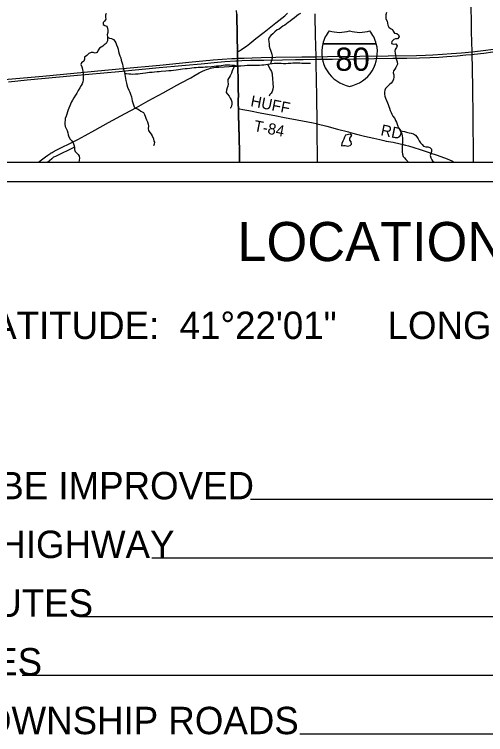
# Model space of a CAD drawing. Extents: x 0 to 34, y 0 to 22.
# Drawn here: x 3.288 to 5.694, y 11.175 to 14.854 of the extents above; entities that cross this region are included whole.
import ezdxf

# ---------------------------------------------------------------- set-up
doc = ezdxf.new("R2010")
doc.units = 0
for name, color, linetype in [('GM_X_Corporation', 7, 'Continuous'), ('GM_X_County_Road', 7, 'Continuous'), ('GM_X_Interstate_Location', 7, 'Continuous'), ('GM_X_Interstate_Route', 7, 'Continuous'), ('GM_X_Interstate_Shield', 7, 'Continuous'), ('GM_X_Minor_Lake', 7, 'Continuous'), ('GM_X_Minor_River', 7, 'Continuous'), ('GM_X_Township_Road', 7, 'Continuous'), ('GM_X_Township_Road_Text', 7, 'Continuous'), ('SH_Data', 7, 'Continuous'), ('SH_Text', 7, 'Continuous')]:
    doc.layers.add(name, color=color, linetype=linetype)

msp = doc.modelspace()

# ---------------------------------------------------------------- linework, layer by layer
at = {"layer": 'GM_X_Corporation'}
for points in [[(2.1, 20.7089), (2.1, 14.1), (8.9, 14.1), (8.9, 18.9067)], [(2.1, 16.8894), (2.1, 14.1), (4.4374, 14.1), (4.437, 14.154), (4.4348, 14.2876), (4.4332, 14.3373), (4.4327, 14.3684), (4.4325, 14.3733), (4.4317, 14.396), (4.4315, 14.4227), (4.4318, 14.4347), (4.431, 14.4741), (4.4301, 14.5114), (4.4285, 14.5905), (4.4282, 14.5944), (4.4282, 14.6082), (4.4279, 14.6184), (4.4276, 14.6307), (4.4274, 14.64), (4.4269, 14.6591), (4.427, 14.6635), (4.4253, 14.7443), (4.4234, 14.8562)], [(4.4234, 14.8562), (4.4253, 14.7443), (4.427, 14.6635), (4.4269, 14.6591), (4.4274, 14.64), (4.4276, 14.6307), (4.4279, 14.6184), (4.4282, 14.6082), (4.4282, 14.5944), (4.4285, 14.5905), (4.4301, 14.5114), (4.431, 14.4741), (4.4318, 14.4347), (4.4315, 14.4227), (4.4317, 14.396), (4.4325, 14.3733), (4.4327, 14.3684), (4.4332, 14.3373), (4.4348, 14.2876), (4.437, 14.154), (4.4374, 14.1), (8.9, 14.1), (8.9, 16.8293)]]:
    msp.add_lwpolyline(points, dxfattribs=at)
at = {"layer": 'GM_X_County_Road'}
for points in [[(4.4272, 14.6629), (4.4314, 14.6655), (4.437, 14.6682), (4.4477, 14.6746), (4.4606, 14.6831), (4.4732, 14.6921), (4.4904, 14.7053), (4.5217, 14.7306), (4.5629, 14.7632), (4.6233, 14.8111), (4.6689, 14.8478), (4.6835, 14.8602)], [(4.4287, 14.5899), (4.4285, 14.5939), (4.4284, 14.6077), (4.4281, 14.6178), (4.4278, 14.6302), (4.4276, 14.6394), (4.4271, 14.6586), (4.4272, 14.6629)], [(3.4111, 14.1), (3.4199, 14.1063), (3.4471, 14.1269), (3.4598, 14.1358), (3.4744, 14.1451), (3.4761, 14.1465), (3.4806, 14.1494), (3.4859, 14.1523), (3.5022, 14.1607), (3.5985, 14.2083), (3.6116, 14.2154), (3.6495, 14.2364), (3.6987, 14.2629), (3.7696, 14.3016), (3.8542, 14.3476), (3.9114, 14.3789), (3.971, 14.4121), (4.0474, 14.4537), (4.1181, 14.4924), (4.1399, 14.5041), (4.189, 14.531), (4.2106, 14.5432), (4.2324, 14.5551), (4.2489, 14.5637), (4.2601, 14.5689), (4.2687, 14.5725), (4.2804, 14.5766), (4.2893, 14.5792), (4.2983, 14.5814), (4.3074, 14.5831), (4.3166, 14.5843), (4.332, 14.5856), (4.4127, 14.5895), (4.4235, 14.5898), (4.4287, 14.5899)]]:
    msp.add_lwpolyline(points, dxfattribs=at)
at = {"layer": 'GM_X_Interstate_Route'}
for points in [[(3.217, 14.5193), (3.4336, 14.5396), (3.7493, 14.5694), (3.8421, 14.5779), (4.0309, 14.5957), (4.1794, 14.6098), (4.3032, 14.6215), (4.3497, 14.6253), (4.3993, 14.6286), (4.4179, 14.6295), (4.4278, 14.6302), (4.4614, 14.6315), (4.5018, 14.6332), (4.5484, 14.6343), (4.623, 14.6351), (4.7566, 14.6371), (4.8286, 14.6382), (4.8871, 14.6391), (5.0519, 14.6411), (5.3409, 14.6451), (5.3875, 14.6462), (5.4248, 14.6477), (5.4744, 14.6506), (5.5209, 14.654), (5.5705, 14.6584), (5.6253, 14.6639), (5.6385, 14.6653), (5.6817, 14.6703), (5.7341, 14.6774)], [(3.2576, 14.5102), (3.3535, 14.5193), (3.5917, 14.5419), (3.6691, 14.5494), (3.8208, 14.5633), (3.9043, 14.571), (3.9601, 14.576), (4.0281, 14.5825), (4.1055, 14.5899), (4.1612, 14.5953), (4.2417, 14.6026), (4.3252, 14.6106), (4.3624, 14.6135), (4.4183, 14.6171), (4.4281, 14.6178), (4.4494, 14.6188), (4.496, 14.6202), (4.5613, 14.6213), (4.6576, 14.6226), (4.7229, 14.6235), (4.7633, 14.6241), (4.8254, 14.6249), (4.8288, 14.6249), (4.869, 14.6256), (4.9124, 14.6262), (5.0336, 14.6281), (5.1268, 14.629), (5.2201, 14.6303), (5.2916, 14.6311), (5.3568, 14.6326), (5.4096, 14.6343), (5.4561, 14.6364), (5.4964, 14.6389), (5.5491, 14.643), (5.5924, 14.647), (5.6256, 14.6502), (5.6357, 14.6511), (5.6851, 14.657), (5.7312, 14.6632)]]:
    msp.add_lwpolyline(points, dxfattribs=at)
at = {"layer": 'GM_X_Interstate_Shield'}
for p, q in [((4.8629, 14.7039), (5.1362, 14.7039)), ((5.1362, 14.7039), (4.8629, 14.7039)), ((5.1362, 14.7039), (4.8629, 14.7039))]:
    msp.add_line(p, q, dxfattribs=at)
for centre, start, end in [((5.0351, 14.6604), 141.669, 165.8066), ((4.9477, 14.9403), 253.0091, 286.9909), ((5.0514, 14.9403), 253.0091, 286.9909), ((4.964, 14.6604), 14.1934, 38.331), ((5.0351, 14.6604), 165.8066, 258.463), ((4.964, 14.6604), 281.537, 14.1934)]:
    msp.add_arc(centre, 0.1776, start, end, dxfattribs=at)
at = {"layer": 'GM_X_Minor_Lake'}
for points in [[(4.967, 14.2108), (4.9653, 14.2066), (4.9597, 14.194), (4.9579, 14.1826), (4.9685, 14.1838), (4.978, 14.1842), (4.9913, 14.1809), (5.0023, 14.1851), (5.0099, 14.1913), (5.0071, 14.203), (5.0002, 14.211), (5.0002, 14.222), (5.0069, 14.2293), (5.0118, 14.2377), (5.0023, 14.2426), (4.9784, 14.2371)], [(4.9784, 14.2371), (4.9735, 14.2268), (4.9698, 14.2176), (4.967, 14.2108)]]:
    msp.add_lwpolyline(points, dxfattribs=at)
at = {"layer": 'GM_X_Minor_River'}
for points in [[(3.7569, 14.8597), (3.754, 14.8505), (3.7536, 14.8399), (3.756, 14.8304), (3.7477, 14.8205), (3.7409, 14.8124), (3.7421, 14.8026), (3.7509, 14.7984), (3.76, 14.7939), (3.7639, 14.7848), (3.7655, 14.7723), (3.7648, 14.7613), (3.7622, 14.7498), (3.7631, 14.7396), (3.7639, 14.7293), (3.7636, 14.7187), (3.7561, 14.7061), (3.7474, 14.6988), (3.7395, 14.6923), (3.7312, 14.6869), (3.7221, 14.6819), (3.7168, 14.6709), (3.7104, 14.6598), (3.7002, 14.6559), (3.6907, 14.66)], [(4.7484, 14.8598), (4.7394, 14.8537), (4.728, 14.8453), (4.7182, 14.8361), (4.7073, 14.8276), (4.6967, 14.8204), (4.6857, 14.8134), (4.677, 14.8058), (4.6683, 14.8), (4.6592, 14.7939), (4.6498, 14.7881), (4.6396, 14.7793), (4.6301, 14.7747), (4.6177, 14.7647), (4.6071, 14.7559), (4.598, 14.7471), (4.5897, 14.7372), (4.586, 14.7269), (4.5872, 14.7159), (4.5884, 14.703), (4.5897, 14.6916), (4.592, 14.6806), (4.5955, 14.6711), (4.5998, 14.6608), (4.6036, 14.6514), (4.6052, 14.6415), (4.6038, 14.6308), (4.6008, 14.6183), (4.5958, 14.6017)], [(5.1887, 14.8641), (5.185, 14.8523), (5.1843, 14.8405), (5.1855, 14.831), (5.1909, 14.8204), (5.1933, 14.809), (5.1956, 14.7988), (5.2002, 14.7893), (5.2083, 14.7821), (5.2186, 14.778), (5.2224, 14.7685), (5.2297, 14.7591), (5.2415, 14.7561), (5.2503, 14.7505), (5.2523, 14.7391), (5.2443, 14.7299), (5.2349, 14.7291), (5.225, 14.7264), (5.2152, 14.7164), (5.2137, 14.7065), (5.2244, 14.702), (5.2366, 14.7033), (5.2427, 14.6945), (5.239, 14.685), (5.2326, 14.6759), (5.2311, 14.666), (5.2327, 14.6557), (5.2335, 14.6439), (5.2363, 14.6344), (5.2401, 14.6227), (5.2433, 14.6113), (5.2441, 14.5999), (5.2355, 14.5839), (5.2306, 14.5747), (5.2246, 14.5659), (5.222, 14.5553), (5.2251, 14.5454), (5.2263, 14.5344), (5.2237, 14.5234), (5.2189, 14.5123), (5.2121, 14.5035), (5.2034, 14.497), (5.194, 14.4867), (5.1838, 14.4763), (5.1789, 14.4672), (5.1775, 14.4569), (5.1783, 14.4474), (5.1803, 14.4364), (5.1834, 14.4269), (5.1884, 14.4144), (5.1938, 14.4027), (5.1969, 14.3936), (5.2004, 14.3837), (5.2035, 14.3746), (5.2077, 14.3636), (5.212, 14.3537), (5.2162, 14.345), (5.2212, 14.3348), (5.2308, 14.3219), (5.2347, 14.3124), (5.2386, 14.3033), (5.2424, 14.2935), (5.2467, 14.2836), (5.2513, 14.2738), (5.2563, 14.2643), (5.2621, 14.2533), (5.2663, 14.2438), (5.2687, 14.234)], [(3.7632, 14.7376), (3.7741, 14.7328), (3.7844, 14.7306), (3.7936, 14.7257), (3.8008, 14.7181), (3.8062, 14.7091), (3.8093, 14.6988), (3.8143, 14.6871), (3.8178, 14.6768), (3.8206, 14.6654), (3.8241, 14.6529), (3.8272, 14.6423), (3.8311, 14.632), (3.8342, 14.6214), (3.8373, 14.61), (3.84, 14.5994), (3.842, 14.5899), (3.8443, 14.5789), (3.8475, 14.569), (3.8498, 14.5584), (3.8518, 14.5478), (3.8537, 14.5375), (3.8553, 14.5269), (3.8581, 14.5163), (3.8608, 14.5037), (3.862, 14.4939), (3.8659, 14.4832), (3.8732, 14.4677), (3.8775, 14.4571), (3.8817, 14.4461), (3.8856, 14.4332), (3.888, 14.4229), (3.8899, 14.4134), (3.8938, 14.4021), (3.8973, 14.3922), (3.9004, 14.3827), (3.9069, 14.3748), (3.9164, 14.3714), (3.926, 14.3661), (3.9347, 14.3601), (3.947, 14.353), (3.952, 14.3424), (3.9558, 14.3336), (3.9593, 14.3245), (3.9628, 14.3151), (3.9674, 14.3052), (3.9713, 14.2938), (3.9729, 14.2828), (3.9718, 14.2718), (3.973, 14.2615), (3.9799, 14.2517), (3.9872, 14.2426), (3.9926, 14.2347), (3.9992, 14.2191), (4.0011, 14.207), (4.0031, 14.2013), (4.0028, 14.1906), (3.9983, 14.1822)], [(3.6907, 14.66), (3.6804, 14.6592), (3.6691, 14.6554), (3.6581, 14.6443), (3.6464, 14.6362), (3.6469, 14.6256), (3.6435, 14.6153), (3.6314, 14.6072), (3.6281, 14.5981), (3.6323, 14.5871), (3.6358, 14.5738), (3.6382, 14.5624), (3.6398, 14.5502), (3.6399, 14.5407), (3.6392, 14.5297), (3.6389, 14.5202), (3.6378, 14.5095), (3.6348, 14.5004), (3.6299, 14.4913), (3.6224, 14.4798), (3.6142, 14.4653), (3.607, 14.4523), (3.6003, 14.4409), (3.5924, 14.4287), (3.5852, 14.4168), (3.5796, 14.4077), (3.5751, 14.3959), (3.5718, 14.3867), (3.5669, 14.3757), (3.5628, 14.3669), (3.5594, 14.3566), (3.5557, 14.3452), (3.552, 14.3338), (3.5479, 14.3231), (3.5468, 14.3132), (3.5461, 14.3037), (3.5454, 14.2938), (3.5482, 14.2816), (3.5524, 14.2718), (3.5571, 14.2612), (3.5606, 14.2498), (3.5637, 14.2388), (3.5668, 14.2293), (3.5733, 14.2176), (3.5821, 14.2089), (3.5883, 14.1979), (3.5918, 14.1876), (3.5945, 14.1763), (3.595, 14.1641), (3.5992, 14.1542), (3.6061, 14.1474), (3.6145, 14.1391), (3.6195, 14.1297), (3.6207, 14.1198), (3.6193, 14.1095), (3.6167, 14.1)], [(3.851, 14.5518), (3.8609, 14.552), (3.8723, 14.5506), (3.8825, 14.5503), (3.8932, 14.5496), (3.9068, 14.55), (3.9198, 14.5512), (3.9304, 14.5521), (3.9448, 14.5544), (3.9585, 14.5564), (3.968, 14.5576), (3.9786, 14.5585), (3.9911, 14.5597), (4.0036, 14.5609), (4.0177, 14.5621), (4.0279, 14.563), (4.0374, 14.5638), (4.061, 14.5654), (4.0773, 14.5674), (4.0891, 14.5683), (4.1008, 14.5695), (4.1141, 14.5715), (4.1259, 14.5727), (4.1358, 14.5739), (4.146, 14.5755), (4.1604, 14.5779), (4.171, 14.5783), (4.184, 14.5803), (4.1946, 14.5819), (4.206, 14.5831), (4.2158, 14.5835), (4.2269, 14.5844), (4.2386, 14.5848), (4.2515, 14.5853), (4.2629, 14.5857), (4.2739, 14.5866), (4.2948, 14.5886), (4.3077, 14.5902), (4.321, 14.5914), (4.3313, 14.5922), (4.3438, 14.5935), (4.3548, 14.5947), (4.365, 14.5963), (4.3764, 14.5959), (4.3882, 14.596), (4.3992, 14.5957), (4.4099, 14.5943), (4.4221, 14.5921), (4.4323, 14.5914), (4.4437, 14.5914), (4.4627, 14.5938), (4.476, 14.5947), (4.4878, 14.5947), (4.4988, 14.5948), (4.5094, 14.5953), (4.5193, 14.5953), (4.5292, 14.5954), (4.5402, 14.5955), (4.5512, 14.5959), (4.5626, 14.5971), (4.5728, 14.5983), (4.5823, 14.5999), (4.5926, 14.6011), (4.6043, 14.6031), (4.615, 14.6047), (4.626, 14.6051), (4.6404, 14.6052), (4.6499, 14.6045), (4.6621, 14.6042), (4.6742, 14.6043), (4.6868, 14.6047), (4.7, 14.606), (4.7107, 14.6064), (4.7236, 14.6065), (4.735, 14.6066), (4.7449, 14.6063), (4.7563, 14.6056), (4.7692, 14.6053), (4.7817, 14.605), (4.792, 14.6054), (4.8003, 14.6058)], [(4.4104, 14.5942), (4.4081, 14.5847), (4.401, 14.5657), (4.3961, 14.5535), (4.3901, 14.5409), (4.3841, 14.5317), (4.3789, 14.5222), (4.3786, 14.5104), (4.3798, 14.4998), (4.3787, 14.488), (4.375, 14.4785), (4.372, 14.4667), (4.3698, 14.4556), (4.3771, 14.4465), (4.3855, 14.4363), (4.3902, 14.4265), (4.3948, 14.4178), (4.3979, 14.4083), (4.3987, 14.398), (4.3961, 14.3862), (4.3913, 14.3752), (4.3905, 14.3748)], [(4.5799, 14.5995), (4.5954, 14.5711), (4.6016, 14.5628), (4.6039, 14.5514), (4.6044, 14.5411), (4.6056, 14.5316), (4.606, 14.5202), (4.6073, 14.5092), (4.6085, 14.4993), (4.609, 14.4841), (4.6087, 14.4723), (4.6053, 14.4613), (4.5997, 14.4525), (4.5929, 14.4449), (4.5892, 14.4361)], [(5.259, 14.2591), (5.2696, 14.2583), (5.2799, 14.2553), (5.291, 14.252), (5.3039, 14.2486), (5.3142, 14.2472), (5.3256, 14.2442), (5.3363, 14.2378), (5.3432, 14.2284), (5.3493, 14.2185), (5.3547, 14.2083), (5.3616, 14.1984), (5.3696, 14.1897), (5.3777, 14.1818), (5.3891, 14.1785), (5.3986, 14.1774), (5.4089, 14.174), (5.4173, 14.1661), (5.4174, 14.1547), (5.4137, 14.1437), (5.4118, 14.133), (5.4138, 14.1216), (5.4192, 14.111), (5.4253, 14.1023), (5.4396, 14.1)], [(5.2687, 14.234), (5.2703, 14.223), (5.2707, 14.2127), (5.2704, 14.1998), (5.2682, 14.1868), (5.2683, 14.1739), (5.2684, 14.1621), (5.2689, 14.1519), (5.2697, 14.1401), (5.2736, 14.1283), (5.2793, 14.1208), (5.2874, 14.1124), (5.2946, 14.1053), (5.2956, 14.1)], [(3.5945, 14.176), (3.498, 14.1285), (3.4885, 14.1243), (3.4794, 14.117), (3.4673, 14.1059), (3.4597, 14.1)]]:
    msp.add_lwpolyline(points, dxfattribs=at)
at = {"layer": 'GM_X_Township_Road'}
for points in [[(5.623, 14.7648), (5.6223, 14.7968), (5.6202, 14.9118), (5.6194, 14.9584), (5.6189, 14.9816)], [(4.4272, 14.6629), (4.4255, 14.7437), (4.4236, 14.8556), (4.4231, 14.875)], [(4.8339, 14.2956), (4.8334, 14.3442), (4.8329, 14.3908), (4.8324, 14.4592), (4.8316, 14.4965), (4.8288, 14.6249), (4.8286, 14.6382), (4.8273, 14.6954), (4.825, 14.7469), (4.8238, 14.8477), (4.8233, 14.857)], [(5.6274, 14.5685), (5.6272, 14.5794), (5.6256, 14.6502), (5.6253, 14.6639), (5.623, 14.7648)], [(4.4287, 14.5899), (4.4285, 14.5939), (4.4284, 14.6077), (4.4281, 14.6178), (4.4278, 14.6302), (4.4276, 14.6394), (4.4271, 14.6586), (4.4272, 14.6629)], [(4.4327, 14.3728), (4.4319, 14.3955), (4.4317, 14.4222), (4.432, 14.4341), (4.4312, 14.4736), (4.4303, 14.5108), (4.4287, 14.5899)], [(5.6318, 14.1), (5.6316, 14.204), (5.6313, 14.2506), (5.6309, 14.2941), (5.6304, 14.3377), (5.6302, 14.381), (5.6293, 14.4284), (5.6292, 14.4878), (5.6274, 14.5685)], [(4.4327, 14.3728), (4.4399, 14.3715), (4.4551, 14.3689), (4.4849, 14.3628), (4.5516, 14.3501), (4.6188, 14.3375), (4.6675, 14.3278), (4.7316, 14.3156), (4.814, 14.3001), (4.8292, 14.2968), (4.8339, 14.2956)], [(4.4377, 14.1), (4.4372, 14.1535), (4.435, 14.2871), (4.4334, 14.3368), (4.4329, 14.3679), (4.4327, 14.3728)], [(4.8339, 14.2956), (4.8833, 14.2828), (4.9373, 14.2685), (4.9943, 14.2536), (5.0027, 14.2512), (5.0489, 14.2387), (5.0758, 14.2328), (5.1236, 14.2226), (5.1534, 14.2148), (5.1747, 14.2098), (5.1868, 14.2075), (5.199, 14.2051), (5.2221, 14.2011), (5.2581, 14.1936), (5.2672, 14.1918), (5.2852, 14.187), (5.2999, 14.183), (5.3286, 14.1745), (5.3598, 14.1644), (5.4003, 14.1505), (5.4147, 14.1455), (5.441, 14.1362), (5.4843, 14.1213), (5.4985, 14.1156), (5.5213, 14.1058), (5.5342, 14.1)], [(4.8357, 14.1), (4.8352, 14.1514), (4.8346, 14.2198), (4.8341, 14.2789), (4.8339, 14.2956)]]:
    msp.add_lwpolyline(points, dxfattribs=at)
at = {"layer": 'SH_Data'}
for p, q in [((2.1, 14.1), (8.9, 14.1)), ((2, 14), (9, 14)), ((7.7, 12.3767), (4.4937, 12.3767)), ((7.7, 12.0767), (3.9895, 12.0767)), ((7.7, 11.7767), (3.6192, 11.7767)), ((7.7, 11.4767), (3.3288, 11.4767)), ((7.7, 11.1767), (4.7452, 11.1767))]:
    msp.add_line(p, q, dxfattribs=at)

# ---------------------------------------------------------------- texts
at = {"layer": 'GM_X_Interstate_Location'}
for s in ['-', '.', ',']:
    msp.add_text(s, height=0.000189, dxfattribs=at).set_placement((4.9995, 14.6284))
msp.add_text('80', height=0.000189, rotation=0, dxfattribs=at).set_placement((4.9608, 14.5892))
at = {"layer": 'GM_X_Interstate_Shield'}
msp.add_text('80', height=0.11837, dxfattribs=at).set_placement((4.9268, 14.5663))
at = {"layer": 'GM_X_Township_Road_Text'}
for s, rotation, p in [('HUFF', 348.901, (4.491, 14.3858)), ('T-84', 349.0345, (4.5074, 14.2588)), ('RD', 348.5969, (5.1554, 14.2374))]:
    msp.add_text(s, height=0.05682, rotation=rotation, dxfattribs=at).set_placement(p)
at = {"layer": 'SH_Text'}
for s, height, p in [('LOCATION MAP', 0.2, (4.4269, 13.5938)), ('LATITUDE:  41°22\'01"     LONGITUDE:  82°30\'43"', 0.14, (3.071, 13.1959)), ('PORTION TO BE IMPROVED', 0.14, (1.9944, 12.3767)), ('INTERSTATE HIGHWAY', 0.14, (1.9944, 12.0767)), ('FEDERAL ROUTES', 0.14, (1.9944, 11.7767)), ('STATE ROUTES', 0.14, (1.9944, 11.4767)), ('COUNTY & TOWNSHIP ROADS', 0.14, (1.9944, 11.1767))]:
    msp.add_text(s, height=height, dxfattribs=at).set_placement(p)

doc.saveas('drawing.dxf')
